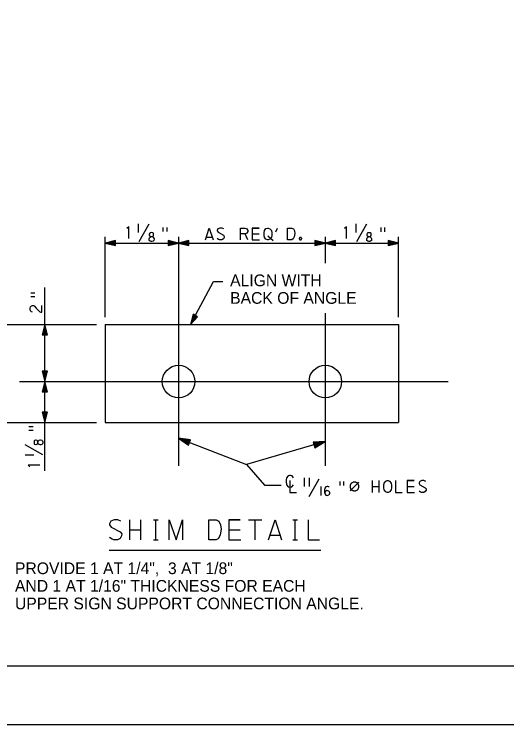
# Model space of a CAD drawing. Extents: x 3829340 to 3831660, y 499389 to 501171.
# Drawn here: x 3830679.9 to 3830805.8, y 499389.2 to 499570.9 of the extents above; entities that cross this region are included whole.
import ezdxf

# ---------------------------------------------------------------- set-up
doc = ezdxf.new("R2010")
doc.units = 0
for name, color, linetype in [('10', 7, 'Continuous'), ('11', 7, 'Continuous'), ('2', 7, 'Continuous'), ('21', 7, 'Continuous'), ('PLT-BNDY', 7, 'Continuous')]:
    doc.layers.add(name, color=color, linetype=linetype)

msp = doc.modelspace()

# ---------------------------------------------------------------- linework, layer by layer
at = {"layer": '10'}
for p, q in [((3830709.15, 499516.56), (3830708.67, 499516.08)), ((3830709.15, 499513.56), (3830709.15, 499516.56)), ((3830711.67, 499515.07), (3830711.67, 499517.31)), ((3830711.79, 499512.8), (3830714.34, 499517.31)), ((3830718, 499515.3), (3830718, 499516.37)), ((3830718.95, 499515.3), (3830718.95, 499516.37)), ((3830740.74, 499516.22), (3830742.47, 499516.22)), ((3830746.74, 499515.22), (3830747.22, 499516.22)), ((3830764.78, 499516.53), (3830764.31, 499516.06)), ((3830764.78, 499513.53), (3830764.78, 499516.53)), ((3830767.31, 499515.04), (3830767.31, 499517.29)), ((3830767.43, 499512.78), (3830769.98, 499517.29)), ((3830773.64, 499515.28), (3830773.64, 499516.34)), ((3830774.59, 499515.28), (3830774.59, 499516.34)), ((3830739.61, 499513.22), (3830738.93, 499514.75)), ((3830740.74, 499514.73), (3830742.47, 499514.73)), ((3830740.74, 499514.73), (3830742.47, 499514.73)), ((3830746.06, 499512.91), (3830744.74, 499514.16)), ((3830703.15, 499493.43), (3830703.15, 499513.94)), ((3830705.8, 499513.03), (3830703.15, 499512.37)), ((3830703.15, 499512.37), (3830721.9, 499512.37)), ((3830703.15, 499512.37), (3830705.8, 499511.71)), ((3830705.64, 499512.83), (3830703.8, 499512.37)), ((3830703.8, 499512.37), (3830705.64, 499511.91)), ((3830705.48, 499512.63), (3830704.44, 499512.37)), ((3830704.44, 499512.37), (3830705.48, 499512.11)), ((3830705.42, 499512.45), (3830705.09, 499512.37)), ((3830705.09, 499512.37), (3830705.4, 499512.29)), ((3830705.48, 499512.11), (3830705.48, 499512.63)), ((3830705.64, 499511.91), (3830705.64, 499512.83)), ((3830705.8, 499511.71), (3830705.8, 499513.03)), ((3830721.91, 499512.37), (3830719.26, 499513.03)), ((3830719.26, 499513.03), (3830719.26, 499511.71)), ((3830719.26, 499511.71), (3830721.91, 499512.37)), ((3830721.26, 499512.37), (3830719.42, 499512.83)), ((3830719.42, 499512.83), (3830719.42, 499511.91)), ((3830719.42, 499511.91), (3830721.26, 499512.37)), ((3830720.61, 499512.37), (3830719.58, 499512.63)), ((3830719.58, 499512.63), (3830719.58, 499512.11)), ((3830719.58, 499512.11), (3830720.61, 499512.37)), ((3830719.64, 499512.29), (3830719.97, 499512.37)), ((3830719.97, 499512.37), (3830719.65, 499512.45)), ((3830724.55, 499513.03), (3830721.9, 499512.37)), ((3830721.9, 499512.37), (3830759.4, 499512.37)), ((3830721.9, 499512.37), (3830724.55, 499511.71)), ((3830724.39, 499512.83), (3830722.55, 499512.37)), ((3830722.55, 499512.37), (3830724.39, 499511.91)), ((3830724.23, 499512.63), (3830723.19, 499512.37)), ((3830723.19, 499512.37), (3830724.23, 499512.11)), ((3830724.17, 499512.45), (3830723.84, 499512.37)), ((3830723.84, 499512.37), (3830724.15, 499512.29)), ((3830724.23, 499512.11), (3830724.23, 499512.63)), ((3830724.39, 499511.91), (3830724.39, 499512.83)), ((3830724.55, 499511.71), (3830724.55, 499513.03)), ((3830728.98, 499513.92), (3830730.47, 499513.92)), ((3830759.41, 499512.37), (3830756.76, 499513.03)), ((3830756.76, 499513.03), (3830756.76, 499511.71)), ((3830756.76, 499511.71), (3830759.41, 499512.37)), ((3830758.76, 499512.37), (3830756.92, 499512.83)), ((3830756.92, 499512.83), (3830756.92, 499511.91)), ((3830756.92, 499511.91), (3830758.76, 499512.37)), ((3830758.11, 499512.37), (3830757.08, 499512.63)), ((3830757.08, 499512.63), (3830757.08, 499512.11)), ((3830757.08, 499512.11), (3830758.11, 499512.37)), ((3830757.14, 499512.29), (3830757.47, 499512.37)), ((3830757.47, 499512.37), (3830757.15, 499512.45)), ((3830762.04, 499513.03), (3830759.4, 499512.37)), ((3830759.4, 499512.37), (3830778.15, 499512.37)), ((3830759.4, 499512.37), (3830762.04, 499511.71)), ((3830761.89, 499512.83), (3830760.05, 499512.37)), ((3830760.05, 499512.37), (3830761.89, 499511.91)), ((3830761.73, 499512.63), (3830760.69, 499512.37)), ((3830760.69, 499512.37), (3830761.73, 499512.11)), ((3830761.67, 499512.45), (3830761.34, 499512.37)), ((3830761.34, 499512.37), (3830761.65, 499512.29)), ((3830761.73, 499512.11), (3830761.73, 499512.63)), ((3830761.89, 499511.91), (3830761.89, 499512.83)), ((3830762.04, 499511.71), (3830762.04, 499513.03)), ((3830778.16, 499512.37), (3830775.51, 499513.03)), ((3830775.51, 499513.03), (3830775.51, 499511.71)), ((3830775.51, 499511.71), (3830778.16, 499512.37)), ((3830777.51, 499512.37), (3830775.67, 499512.83)), ((3830775.67, 499512.83), (3830775.67, 499511.91)), ((3830775.67, 499511.91), (3830777.51, 499512.37)), ((3830776.86, 499512.37), (3830775.83, 499512.63)), ((3830775.83, 499512.63), (3830775.83, 499512.11)), ((3830775.83, 499512.11), (3830776.86, 499512.37)), ((3830775.89, 499512.29), (3830776.22, 499512.37)), ((3830776.22, 499512.37), (3830775.9, 499512.45)), ((3830778.15, 499493.43), (3830778.15, 499513.94)), ((3830724.93, 499491.53), (3830730.79, 499502.53)), ((3830730.79, 499502.53), (3830733.22, 499502.53)), ((3830685.19, 499499.54), (3830684.13, 499499.54)), ((3830687.73, 499491.52), (3830687.73, 499501.02)), ((3830685.19, 499498.59), (3830684.13, 499498.59)), ((3830725.59, 499494.17), (3830724.93, 499491.52)), ((3830726.75, 499493.55), (3830725.59, 499494.17)), ((3830724.93, 499491.52), (3830726.75, 499493.55)), ((3830725.69, 499493.94), (3830725.23, 499492.09)), ((3830725.23, 499492.09), (3830726.5, 499493.5)), ((3830725.79, 499493.7), (3830725.53, 499492.66)), ((3830725.53, 499492.66), (3830726.25, 499493.46)), ((3830726.5, 499493.5), (3830725.69, 499493.94)), ((3830726.25, 499493.46), (3830725.79, 499493.7)), ((3830725.92, 499493.56), (3830725.84, 499493.23)), ((3830725.84, 499493.23), (3830726.05, 499493.47)), ((3830670.06, 499491.52), (3830700.9, 499491.52)), ((3830687.73, 499491.53), (3830687.07, 499488.88)), ((3830687.73, 499490.88), (3830687.27, 499489.04)), ((3830688.39, 499488.88), (3830687.73, 499491.53)), ((3830687.73, 499476.94), (3830687.73, 499491.52)), ((3830688.19, 499489.04), (3830687.73, 499490.88)), ((3830687.07, 499488.88), (3830688.39, 499488.88)), ((3830687.27, 499489.04), (3830688.19, 499489.04)), ((3830687.73, 499490.23), (3830687.47, 499489.2)), ((3830687.47, 499489.2), (3830687.99, 499489.2)), ((3830687.73, 499489.59), (3830687.65, 499489.27)), ((3830687.99, 499489.2), (3830687.73, 499490.23)), ((3830687.81, 499489.26), (3830687.73, 499489.59)), ((3830687.06, 499479.58), (3830687.72, 499476.94)), ((3830688.39, 499479.58), (3830687.06, 499479.58)), ((3830687.72, 499476.94), (3830688.39, 499479.58)), ((3830687.26, 499479.43), (3830687.72, 499477.59)), ((3830688.18, 499479.43), (3830687.26, 499479.43)), ((3830687.47, 499479.27), (3830687.72, 499478.23)), ((3830687.98, 499479.27), (3830687.47, 499479.27)), ((3830687.64, 499479.21), (3830687.72, 499478.88)), ((3830687.72, 499477.59), (3830688.18, 499479.43)), ((3830687.72, 499478.23), (3830687.98, 499479.27)), ((3830687.72, 499478.88), (3830687.8, 499479.19)), ((3830687.73, 499476.95), (3830687.07, 499474.3)), ((3830687.73, 499476.3), (3830687.27, 499474.46)), ((3830688.39, 499474.3), (3830687.73, 499476.95)), ((3830687.73, 499466.52), (3830687.73, 499476.94)), ((3830688.19, 499474.46), (3830687.73, 499476.3)), ((3830687.07, 499474.3), (3830688.39, 499474.3)), ((3830687.27, 499474.46), (3830688.19, 499474.46)), ((3830687.73, 499475.65), (3830687.47, 499474.62)), ((3830687.47, 499474.62), (3830687.99, 499474.62)), ((3830687.73, 499475.01), (3830687.65, 499474.69)), ((3830687.99, 499474.62), (3830687.73, 499475.65)), ((3830687.81, 499474.68), (3830687.73, 499475.01)), ((3830687.06, 499469.17), (3830687.72, 499466.52)), ((3830688.39, 499469.17), (3830687.06, 499469.17)), ((3830687.26, 499469.01), (3830687.72, 499467.17)), ((3830688.18, 499469.01), (3830687.26, 499469.01)), ((3830687.47, 499468.85), (3830687.72, 499467.81)), ((3830687.98, 499468.85), (3830687.47, 499468.85)), ((3830687.64, 499468.79), (3830687.72, 499468.46)), ((3830687.72, 499466.52), (3830688.39, 499469.17)), ((3830687.72, 499467.17), (3830688.18, 499469.01)), ((3830687.72, 499467.81), (3830687.98, 499468.85)), ((3830687.72, 499468.46), (3830687.8, 499468.77)), ((3830670.06, 499466.52), (3830700.9, 499466.52)), ((3830684.69, 499465.4), (3830683.63, 499465.4)), ((3830687.73, 499454.09), (3830687.73, 499466.52)), ((3830684.69, 499464.45), (3830683.63, 499464.45)), ((3830721.9, 499462.47), (3830739.26, 499455.75)), ((3830721.9, 499462.47), (3830724.43, 499460.69)), ((3830724.97, 499462.09), (3830721.9, 499462.47)), ((3830722.59, 499462.21), (3830724.35, 499460.97)), ((3830724.72, 499461.94), (3830722.59, 499462.21)), ((3830724.48, 499461.79), (3830723.27, 499461.94)), ((3830723.27, 499461.94), (3830724.26, 499461.24)), ((3830723.95, 499461.68), (3830724.25, 499461.47)), ((3830724.34, 499461.63), (3830723.95, 499461.68)), ((3830724.26, 499461.24), (3830724.48, 499461.79)), ((3830724.35, 499460.97), (3830724.72, 499461.94)), ((3830724.43, 499460.69), (3830724.97, 499462.09)), ((3830759.4, 499461.61), (3830739.26, 499455.75)), ((3830759.4, 499461.61), (3830756.28, 499461.49)), ((3830756.28, 499461.49), (3830756.7, 499460.03)), ((3830758.69, 499461.4), (3830756.51, 499461.32)), ((3830756.51, 499461.32), (3830756.81, 499460.3)), ((3830756.7, 499460.03), (3830759.4, 499461.61)), ((3830756.81, 499460.3), (3830758.69, 499461.4)), ((3830687.19, 499458.24), (3830682.68, 499460.79)), ((3830757.98, 499461.19), (3830756.75, 499461.15)), ((3830756.75, 499461.15), (3830756.92, 499460.57)), ((3830757.27, 499460.99), (3830756.89, 499460.97)), ((3830756.92, 499460.57), (3830757.98, 499461.19)), ((3830756.93, 499460.79), (3830757.27, 499460.99)), ((3830684.93, 499458.12), (3830682.68, 499458.12)), ((3830686.44, 499455.6), (3830683.44, 499455.6)), ((3830683.44, 499455.6), (3830683.91, 499455.12)), ((3830739.26, 499455.75), (3830743.88, 499450.49)), ((3830754.06, 499450.13), (3830754.06, 499452.37)), ((3830755.36, 499450.13), (3830755.36, 499452.37)), ((3830743.88, 499450.49), (3830748.12, 499450.49)), ((3830755.26, 499447.58), (3830757.82, 499452.09)), ((3830763.23, 499450.36), (3830763.23, 499451.43)), ((3830764.17, 499450.36), (3830764.17, 499451.43)), ((3830765.73, 499448.99), (3830767.97, 499451.24)), ((3830771.35, 499451.62), (3830771.35, 499448.62)), ((3830773.05, 499451.62), (3830773.05, 499448.62)), ((3830780.35, 499451.62), (3830782.08, 499451.62)), ((3830758.34, 499447.86), (3830758.34, 499450.1)), ((3830771.35, 499450.1), (3830773.05, 499450.1)), ((3830780.35, 499450.13), (3830782.08, 499450.13)), ((3830780.35, 499450.13), (3830782.08, 499450.13)), ((3830709.32, 499441.58), (3830709.32, 499436.5)), ((3830712.2, 499441.58), (3830712.2, 499436.5)), ((3830715.52, 499441.58), (3830716.72, 499441.58)), ((3830716.12, 499436.5), (3830716.12, 499441.58)), ((3830734.71, 499441.58), (3830737.63, 499441.58)), ((3830739.79, 499441.58), (3830743.15, 499441.58)), ((3830741.47, 499436.5), (3830741.47, 499441.58)), ((3830741.47, 499436.5), (3830741.47, 499441.58)), ((3830751.06, 499441.58), (3830752.26, 499441.58)), ((3830751.66, 499436.5), (3830751.66, 499441.58)), ((3830709.32, 499439.02), (3830712.2, 499439.02)), ((3830734.71, 499439.06), (3830737.63, 499439.06)), ((3830734.71, 499439.06), (3830737.63, 499439.06)), ((3830745.27, 499437.7), (3830747.79, 499437.7)), ((3830715.52, 499436.5), (3830716.72, 499436.5)), ((3830751.06, 499436.5), (3830752.26, 499436.5)), ((3830704.18, 499433.85), (3830758.22, 499433.85))]:
    msp.add_line(p, q, dxfattribs=at)
for points in [[(3830728.75, 499513.22), (3830729.74, 499516.22), (3830730.71, 499513.22)], [(3830733.47, 499516), (3830733, 499516.22), (3830732.45, 499516.22), (3830731.96, 499516), (3830731.75, 499515.62), (3830731.75, 499515.48), (3830731.98, 499515.13), (3830733.35, 499514.42), (3830733.59, 499514.09), (3830733.56, 499513.81), (3830733.35, 499513.43), (3830732.95, 499513.22), (3830732.38, 499513.22), (3830732.12, 499513.31), (3830731.75, 499513.57)], [(3830737.74, 499513.22), (3830737.74, 499516.22), (3830738.95, 499516.22), (3830739.3, 499516.1), (3830739.61, 499515.62), (3830739.61, 499515.34), (3830739.33, 499514.87), (3830738.95, 499514.75), (3830737.74, 499514.75)], [(3830742.47, 499516.22), (3830740.74, 499516.22), (3830740.74, 499513.22), (3830742.59, 499513.22)], [(3830744.6, 499516.22), (3830744.83, 499516.22), (3830745.23, 499516.05), (3830745.61, 499515.55), (3830745.71, 499514.96), (3830745.71, 499514.42), (3830745.61, 499513.83), (3830745.21, 499513.33), (3830744.83, 499513.22), (3830744.6, 499513.22), (3830744.24, 499513.33), (3830743.84, 499513.83), (3830743.74, 499514.42), (3830743.74, 499514.96), (3830743.84, 499515.58), (3830744.24, 499516.07), (3830744.6, 499516.22)], [(3830749.74, 499516.22), (3830750.83, 499516.22), (3830751.23, 499516), (3830751.49, 499515.48), (3830751.61, 499514.8), (3830751.47, 499513.95), (3830751.21, 499513.43), (3830750.83, 499513.22), (3830749.74, 499513.22), (3830749.74, 499516.22)], [(3830715.1, 499514.05), (3830715.36, 499514.12), (3830715.45, 499514.24), (3830715.52, 499514.5), (3830715.52, 499514.62), (3830715.45, 499514.9), (3830715.33, 499514.97), (3830714.98, 499515.05), (3830714.6, 499514.97), (3830714.51, 499514.9), (3830714.41, 499514.62), (3830714.41, 499514.5), (3830714.48, 499514.24), (3830714.6, 499514.12), (3830714.86, 499514.05), (3830715.1, 499514.05), (3830715.36, 499513.91), (3830715.52, 499513.7), (3830715.62, 499513.46), (3830715.62, 499513.37), (3830715.55, 499513.06), (3830715.36, 499512.87), (3830715.1, 499512.8), (3830714.86, 499512.8), (3830714.6, 499512.87), (3830714.41, 499513.06), (3830714.34, 499513.34), (3830714.34, 499513.46), (3830714.44, 499513.7), (3830714.6, 499513.91), (3830714.86, 499514.05)], [(3830770.74, 499514.03), (3830770.99, 499514.1), (3830771.09, 499514.22), (3830771.16, 499514.48), (3830771.16, 499514.59), (3830771.09, 499514.88), (3830770.97, 499514.95), (3830770.62, 499515.02), (3830770.24, 499514.95), (3830770.14, 499514.88), (3830770.05, 499514.59), (3830770.05, 499514.48), (3830770.12, 499514.22), (3830770.24, 499514.1), (3830770.5, 499514.03), (3830770.74, 499514.03), (3830770.99, 499513.89), (3830771.16, 499513.67), (3830771.25, 499513.44), (3830771.25, 499513.34), (3830771.18, 499513.04), (3830770.99, 499512.85), (3830770.74, 499512.78), (3830770.5, 499512.78), (3830770.24, 499512.85), (3830770.05, 499513.04), (3830769.98, 499513.32), (3830769.98, 499513.44), (3830770.07, 499513.67), (3830770.24, 499513.89), (3830770.5, 499514.03)], [(3830753.36, 499513.52), (3830753.36, 499513.55), (3830753.35, 499513.59), (3830753.34, 499513.62), (3830753.33, 499513.65), (3830753.32, 499513.68), (3830753.3, 499513.7), (3830753.28, 499513.73), (3830753.26, 499513.75), (3830753.23, 499513.77), (3830753.2, 499513.79), (3830753.18, 499513.8), (3830753.15, 499513.81), (3830753.12, 499513.82), (3830753.08, 499513.83), (3830753.05, 499513.83), (3830753.02, 499513.83), (3830752.99, 499513.82), (3830752.96, 499513.81), (3830752.93, 499513.8), (3830752.9, 499513.79), (3830752.87, 499513.77), (3830752.85, 499513.75), (3830752.82, 499513.73), (3830752.8, 499513.7), (3830752.79, 499513.68), (3830752.77, 499513.65), (3830752.76, 499513.62), (3830752.75, 499513.59), (3830752.75, 499513.55), (3830752.74, 499513.52), (3830752.75, 499513.49), (3830752.75, 499513.46), (3830752.76, 499513.43), (3830752.77, 499513.4), (3830752.79, 499513.37), (3830752.8, 499513.34), (3830752.82, 499513.32), (3830752.85, 499513.29), (3830752.87, 499513.27), (3830752.9, 499513.26), (3830752.93, 499513.24), (3830752.96, 499513.23), (3830752.99, 499513.22), (3830753.02, 499513.22), (3830753.05, 499513.22), (3830753.08, 499513.22), (3830753.12, 499513.22), (3830753.15, 499513.23), (3830753.18, 499513.24), (3830753.2, 499513.26), (3830753.23, 499513.27), (3830753.26, 499513.29), (3830753.28, 499513.32), (3830753.3, 499513.34), (3830753.32, 499513.37), (3830753.33, 499513.4), (3830753.34, 499513.43), (3830753.35, 499513.46), (3830753.36, 499513.49), (3830753.36, 499513.52)], [(3830684.55, 499494.72), (3830684.27, 499494.81), (3830684.03, 499495.07), (3830683.94, 499495.43), (3830683.94, 499495.69), (3830684.03, 499496.04), (3830684.29, 499496.3), (3830684.55, 499496.42), (3830684.81, 499496.42), (3830685.02, 499496.32), (3830685.47, 499495.73), (3830686.42, 499494.81), (3830686.65, 499494.72), (3830686.94, 499494.72), (3830686.94, 499496.42)], [(3830685.94, 499461.55), (3830685.87, 499461.81), (3830685.75, 499461.9), (3830685.49, 499461.97), (3830685.37, 499461.97), (3830685.09, 499461.9), (3830685.02, 499461.79), (3830684.95, 499461.43), (3830685.02, 499461.05), (3830685.09, 499460.96), (3830685.37, 499460.86), (3830685.49, 499460.86), (3830685.75, 499460.94), (3830685.87, 499461.05), (3830685.94, 499461.31), (3830685.94, 499461.55), (3830686.08, 499461.81), (3830686.3, 499461.97), (3830686.53, 499462.07), (3830686.63, 499462.07), (3830686.93, 499462), (3830687.12, 499461.81), (3830687.19, 499461.55), (3830687.19, 499461.31), (3830687.12, 499461.05), (3830686.93, 499460.86), (3830686.65, 499460.79), (3830686.53, 499460.79), (3830686.3, 499460.89), (3830686.08, 499461.05), (3830685.94, 499461.31)], [(3830751.28, 499452.37), (3830750.9, 499452.87), (3830750.53, 499452.96), (3830750.27, 499452.96), (3830749.91, 499452.87), (3830749.51, 499452.37), (3830749.42, 499451.71), (3830749.42, 499451.36), (3830749.42, 499451.12), (3830749.44, 499450.91), (3830749.51, 499450.53), (3830749.91, 499450.06), (3830750.27, 499449.96), (3830750.48, 499449.96), (3830750.88, 499450.06), (3830751.28, 499450.53)], [(3830750.35, 499451.62), (3830750.35, 499448.62), (3830752.05, 499448.62)], [(3830767.98, 499450.13), (3830767.97, 499450.25), (3830767.95, 499450.36), (3830767.92, 499450.48), (3830767.88, 499450.58), (3830767.83, 499450.69), (3830767.76, 499450.79), (3830767.69, 499450.88), (3830767.61, 499450.96), (3830767.51, 499451.04), (3830767.42, 499451.1), (3830767.31, 499451.16), (3830767.2, 499451.2), (3830767.09, 499451.23), (3830766.97, 499451.25), (3830766.85, 499451.25), (3830766.74, 499451.25), (3830766.62, 499451.23), (3830766.51, 499451.2), (3830766.4, 499451.16), (3830766.29, 499451.1), (3830766.19, 499451.04), (3830766.1, 499450.96), (3830766.02, 499450.88), (3830765.94, 499450.79), (3830765.88, 499450.69), (3830765.83, 499450.58), (3830765.78, 499450.48), (3830765.75, 499450.36), (3830765.73, 499450.25), (3830765.73, 499450.13), (3830765.73, 499450.01), (3830765.75, 499449.89), (3830765.78, 499449.78), (3830765.83, 499449.67), (3830765.88, 499449.56), (3830765.94, 499449.47), (3830766.02, 499449.37), (3830766.1, 499449.29), (3830766.19, 499449.22), (3830766.29, 499449.15), (3830766.4, 499449.1), (3830766.51, 499449.06), (3830766.62, 499449.03), (3830766.74, 499449.01), (3830766.85, 499449), (3830766.97, 499449.01), (3830767.09, 499449.03), (3830767.2, 499449.06), (3830767.31, 499449.1), (3830767.42, 499449.15), (3830767.51, 499449.22), (3830767.61, 499449.29), (3830767.69, 499449.37), (3830767.76, 499449.47), (3830767.83, 499449.56), (3830767.88, 499449.67), (3830767.92, 499449.78), (3830767.95, 499449.89), (3830767.97, 499450.01), (3830767.98, 499450.13)], [(3830775.2, 499451.62), (3830775.44, 499451.62), (3830775.84, 499451.45), (3830776.22, 499450.95), (3830776.31, 499450.36), (3830776.31, 499449.82), (3830776.22, 499449.23), (3830775.82, 499448.73), (3830775.44, 499448.62), (3830775.2, 499448.62), (3830774.85, 499448.73), (3830774.45, 499449.23), (3830774.35, 499449.82), (3830774.35, 499450.36), (3830774.45, 499450.98), (3830774.85, 499451.47), (3830775.2, 499451.62)], [(3830777.35, 499451.62), (3830777.35, 499448.62), (3830779.05, 499448.62)], [(3830782.08, 499451.62), (3830780.35, 499451.62), (3830780.35, 499448.62), (3830782.19, 499448.62)], [(3830785.07, 499451.4), (3830784.6, 499451.62), (3830784.06, 499451.62), (3830783.56, 499451.4), (3830783.35, 499451.03), (3830783.35, 499450.88), (3830783.59, 499450.53), (3830784.96, 499449.82), (3830785.19, 499449.49), (3830785.17, 499449.21), (3830784.96, 499448.83), (3830784.56, 499448.62), (3830783.99, 499448.62), (3830783.73, 499448.71), (3830783.35, 499448.97)], [(3830760.39, 499449.96), (3830760.27, 499450.03), (3830760.06, 499450.1), (3830759.85, 499450.1), (3830759.56, 499450.03), (3830759.26, 499449.66), (3830759.19, 499449.3), (3830759.19, 499448.9), (3830759.23, 499448.57), (3830759.37, 499448.12), (3830759.56, 499447.93), (3830759.85, 499447.86), (3830760.3, 499447.95), (3830760.48, 499448.12), (3830760.58, 499448.4), (3830760.58, 499448.54), (3830760.48, 499448.76), (3830760.3, 499448.97), (3830760.01, 499449.04), (3830759.82, 499449.06), (3830759.54, 499448.97), (3830759.37, 499448.76), (3830759.28, 499448.4)], [(3830707.16, 499441.22), (3830706.36, 499441.58), (3830705.44, 499441.58), (3830704.6, 499441.22), (3830704.24, 499440.58), (3830704.24, 499440.34), (3830704.64, 499439.74), (3830706.96, 499438.54), (3830707.36, 499437.98), (3830707.32, 499437.5), (3830706.96, 499436.86), (3830706.28, 499436.5), (3830705.32, 499436.5), (3830704.88, 499436.66), (3830704.24, 499437.1)], [(3830719.48, 499436.5), (3830719.48, 499441.58), (3830721.24, 499436.5), (3830722.87, 499441.58), (3830722.87, 499436.5)], [(3830729.63, 499441.58), (3830731.47, 499441.58), (3830732.15, 499441.22), (3830732.59, 499440.34), (3830732.79, 499439.18), (3830732.55, 499437.74), (3830732.11, 499436.86), (3830731.47, 499436.5), (3830729.63, 499436.5), (3830729.63, 499441.58)], [(3830737.63, 499441.58), (3830734.71, 499441.58), (3830734.71, 499436.5), (3830737.83, 499436.5)], [(3830744.87, 499436.5), (3830746.55, 499441.58), (3830748.18, 499436.5)], [(3830755.02, 499441.58), (3830755.02, 499436.5), (3830757.9, 499436.5)]]:
    msp.add_lwpolyline(points, dxfattribs=at)
at = {"layer": '11'}
for p, q in [((3830721.9, 499513.94), (3830721.9, 499455.43)), ((3830759.4, 499513.94), (3830759.4, 499507.19)), ((3830759.4, 499494.43), (3830759.4, 499455.44)), ((3830681.22, 499476.94), (3830790.83, 499476.94))]:
    msp.add_line(p, q, dxfattribs=at)
at = {"layer": '2'}
msp.add_line((3831006.96, 499404.19), (3830220.96, 499404.19), dxfattribs=at)
at = {"layer": '21'}
for p, q in [((3830703.15, 499491.52), (3830778.15, 499491.52)), ((3830703.15, 499491.52), (3830703.15, 499466.52)), ((3830778.15, 499491.52), (3830778.15, 499466.52)), ((3830703.15, 499466.52), (3830778.15, 499466.52))]:
    msp.add_line(p, q, dxfattribs=at)
for centre in [(3830721.91, 499476.94), (3830759.41, 499476.94)]:
    msp.add_circle(centre, 4.17, dxfattribs=at)
at = {"layer": 'PLT-BNDY'}
msp.add_lwpolyline([(3830180.96, 499983.19), (3831021.96, 499983.19), (3831021.96, 499389.19), (3830180.96, 499389.19)], close=True, dxfattribs=at)

# ---------------------------------------------------------------- texts
at = {"layer": '10'}
for s, p in [('ALIGN WITH ', (3830735.07, 499501.34)), ('BACK OF ANGLE', (3830735.07, 499496.84)), ('PROVIDE 1 AT 1/4",  3 AT 1/8"', (3830680.08, 499427.71)), ('AND 1 AT 1/16" THICKNESS FOR EACH', (3830680.08, 499423.21)), ('UPPER SIGN SUPPORT CONNECTION ANGLE.', (3830680.08, 499418.71))]:
    msp.add_text(s, height=2.9999, dxfattribs=at).set_placement(p)

doc.saveas('drawing.dxf')
